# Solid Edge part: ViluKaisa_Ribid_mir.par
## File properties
Author: kaisa
Template: Iso Metric Part.par
Last saved by: kaisa
Revision: 3
Application: Solid Edge
Accuracy: 0.990
Username: kaisa
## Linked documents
ViluKaisa_Ribid.par
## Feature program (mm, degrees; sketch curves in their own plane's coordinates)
part copy "CopiedPart_1"
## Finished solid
Body 1: solid body, 55 faces, 135 edges, 90 vertices, 5 separate solids.
  Faces by surface: spline 45, plane 10
  Edges by curve: line 70, spline 45, circle 20
Bounding box of the edges (mm; curved faces can reach further): 191.060 x 77.344 x 43.762, from (-95.5298, 0, 6.2379) to (95.5298, 77.3444, 50).
Planar faces by outward normal: +z 5, -y 5
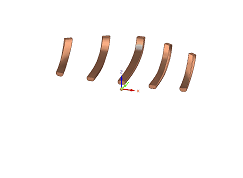
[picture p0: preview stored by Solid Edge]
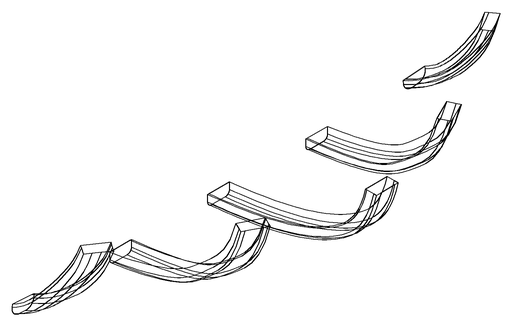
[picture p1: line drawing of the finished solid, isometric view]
